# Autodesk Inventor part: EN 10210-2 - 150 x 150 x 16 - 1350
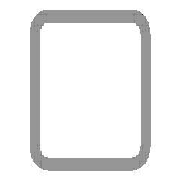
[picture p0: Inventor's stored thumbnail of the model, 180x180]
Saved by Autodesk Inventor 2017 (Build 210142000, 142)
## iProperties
Created: 2017-11
Part Number: EN 10210-2 - 150 x 150 x 16 - 1350
Material: Steel, Mild
Description: Tube
Document SubType Name: Modeling
Standard: DIN
Designer: iusti
Standard Revision: 2006-07
Standards Organization: DIN
Language: en-US
Size Designation: 150 x 150 x 16
Categories: <MemberInstance><Categories><Category DisplayName="Structural Shapes" InternalName="089c4875-fa83-4c05-b084-43b9cc11f5ed" Mnemonic="GRDR"><CategoryParameter Dis
Stock Number: 150 x 150 x 16
Mass: 87973.1 g
Surface Area: 13710.9 cm^2
Volume: 11206.8 cm^3
Density: 7.85 g/cm^3
Appearance: Semi-Polished
_CCFamilyMember: 70
_CCFamilyDisplayName: DIN EN 10210-2 (Square) - Tube — Sizes in parentheses have been withdrawn
_FrameMemberDoc: Frame Member File
_Version: 15.0.0
_GetPNFromCC: 1
IsCustomPart: 1
Author: iusti
G_L: 1350.000 mm
G_W: 150.000 mm
G_H: 150.000 mm
+C47FB281-F24E-4AF7-A30B-302C53F89AE1+CUTDETAIL1: Cut
+CF8FB17E-C026-461A-B8FF-AE5E6F326243+CUTDETAIL2: Cut
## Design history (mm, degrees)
node "Start plane"
node "End plane"
sketch "Sketch"
  geometry: L1 (-75, -51)-(-75, 51); L2 (-51, 75)-(51, 75); L3 (75, 51)-(75, -51); L4 (51, -75)-(-51, -75); L5 (-43, 59)-(43, 59); L6 (59, 43)-(59, -43); L7 (43, -59)-(-43, -59); L8 (-59, -43)-(-59, 43); L9 (0, 111.959)-(0, -111.959) reference; L10 (-111.959, 0)-(111.959, 0) reference; A1 r 24 centre (-51, -51) between (-75, -51) and (-51, -75); A2 r 24 centre (-51, 51) between (-51, 75) and (-75, 51); A3 r 24 centre (51, 51) between (75, 51) and (51, 75); A4 r 24 centre (51, -51) between (51, -75) and (75, -51); A5 r 16 centre (-43, -43) between (-59, -43) and (-43, -59); A6 r 16 centre (-43, 43) between (-43, 59) and (-59, 43); A7 r 16 centre (43, 43) between (59, 43) and (43, 59); A8 r 16 centre (43, -43) between (43, -59) and (59, -43)
  constraints: 16 end point, 16 point on circle, 16 tangent, 8 centre point, 6 equal radius, 4 parallel, 2 perpendicular, 2 other
  dimensions: "d7" = 24 radius of A1 (= G_IR); "d10" = 150 distance between parallel lines of L2 L4 (= G_H); "d11" = 150 distance between parallel lines of L1 L3 (= G_W); "d12" = 16 distance between parallel lines of L3 L6 (= G_T); "d15" = 75 distance between parallel lines of L2 L10 (= 0.5 x d10); "d16" = 75 distance between parallel lines of L9 L3 (= 0.5 x d11); "d19" = 16 radius of A5 (= G_T); "d20" = 16 distance between parallel lines of L4 L7 (= G_T)
extrude "Body" new body sketch "Sketch" stored distance "d3" = 1350 (= G_L); taper "d4" = 0 deg
node "Driven Length"
  sketch "Sketch3"
    geometry: L1 (0, 0)-(10, 0) reference
    constraints: 2 end point, 1 horizontal
  workplane "Work Plane3"
  sketch "Sketch4"
    geometry: L1 (-2, 75)-(12, 75) reference; L2 (-2, 1425)-(12, 1425) reference
    dimensions: "d18" = 1350 distance between parallel lines of L1 L2 (derived)
workplane "Work Plane4"
split "Split1"
workplane "Work Plane5"
split "Split2"
body "Solid1"
other parameters: "G_W" = 150 [user parameter; used in 1 equation term], "G_H" = 150 [user parameter; used in 1 equation term], "G_T" = 16 [user parameter; used in 3 equation terms], "G_IR" = 24 [user parameter; used in 1 equation term], "G_L" = 1350 (= d18) [user parameter; used in 1 equation term], "G_OFFSET_START" = -75 [user parameter; used in 1 equation term], "G_OFFSET_END" = -75 [user parameter; used in 1 equation term], "d13" = 75 (= -G_OFFSET_START), "d14" = 1425 (= G_OFFSET_END + B_L), "d17" = 90 deg
